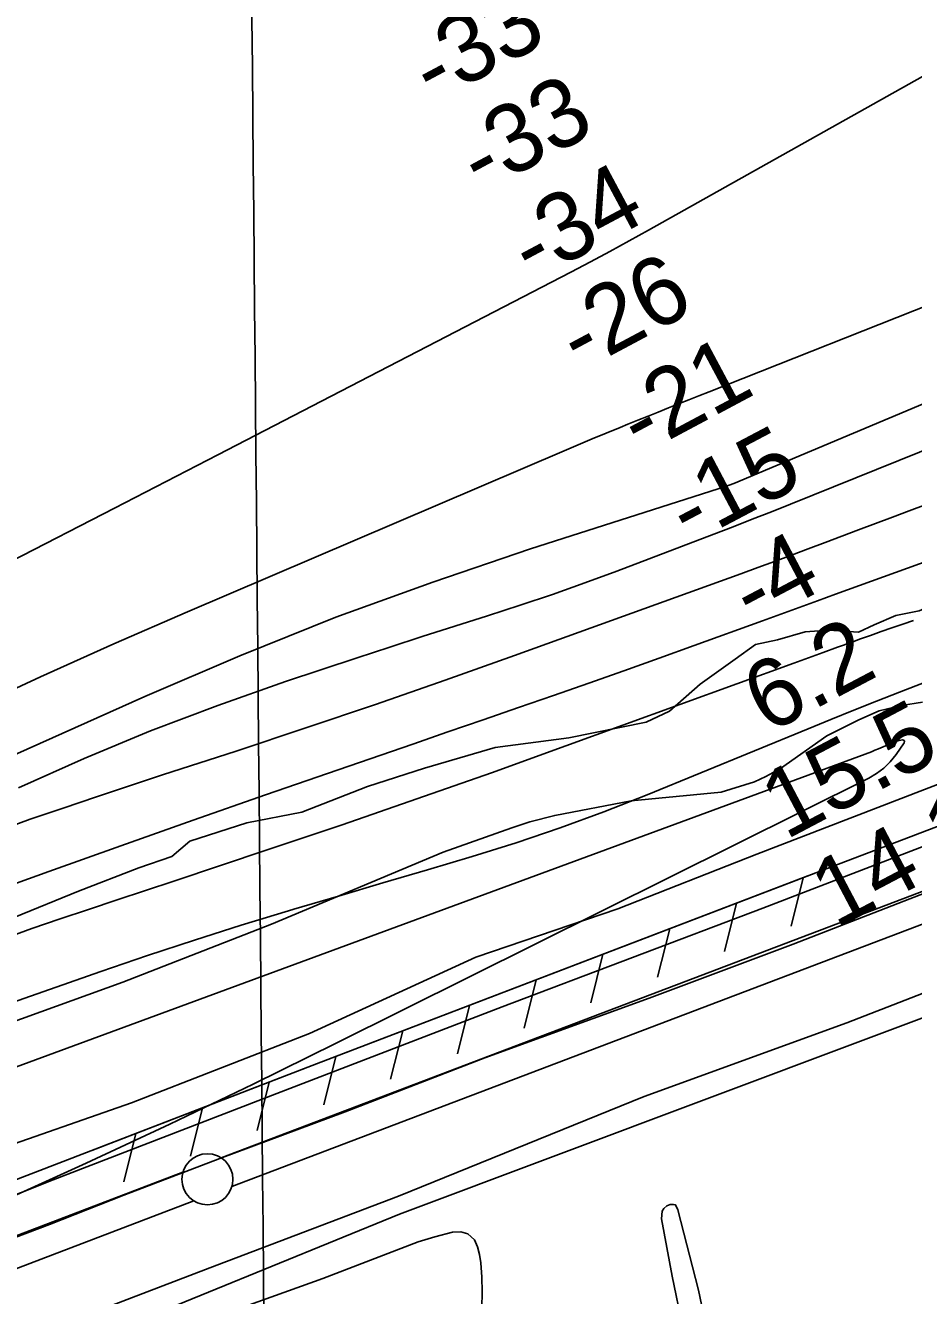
# Model space of a CAD drawing. Extents: x 3598634 to 3636690, y 517270 to 542944.
# Drawn here: x 3613087 to 3613957, y 532459 to 533703 of the extents above; entities that cross this region are included whole.
import ezdxf

# ---------------------------------------------------------------- set-up
doc = ezdxf.new("R2010")
doc.units = 0
for name, color, linetype in [('V-FLOD-BASE', 7, 'Continuous'), ('V-GRID-MAJR', 7, 'Continuous'), ('V-LEVE-TOET', 7, 'Continuous'), ('V-RIVR-EDGE', 7, 'Continuous'), ('V-RIVR-RANG', 7, 'Continuous'), ('V-ROAD-CNTR', 7, 'Continuous'), ('V-RRAP-FSHR', 7, 'Continuous'), ('V-SITE-VEGE', 7, 'Continuous'), ('V-SURV-LINE', 7, 'Continuous'), ('V-TOPO-DPTH', 7, 'Continuous'), ('V-TOPO-MINR', 7, 'Continuous'), ('V-TOPO-WATR', 7, 'Continuous')]:
    doc.layers.add(name, color=color, linetype=linetype)

msp = doc.modelspace()

# ---------------------------------------------------------------- linework, layer by layer
at = {"layer": 'V-FLOD-BASE'}
msp.add_lwpolyline([(3613000.302, 532486.936), (3613110.683, 532528.524), (3613183.67, 532557.436), (3613277.515, 532593.333), (3613400.362, 532638.807), (3613537.187, 532691.742), (3613698.191, 532750.407), (3613839.347, 532803.3640000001), (3613981.257, 532858.363), (3614114.5330000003, 532907.9670000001), (3614199.723, 532942.0380000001), (3614387.173, 533011.7930000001), (3614512.052, 533058.553)], dxfattribs=at)
at = {"layer": 'V-GRID-MAJR'}
msp.add_spline([(3613409.2970000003, 522775.228), (3613353.788, 528832.875), (3613298.25, 534893.607), (3613242.713, 540954.353), (3613242.685, 540957.422)], degree=3, dxfattribs=at)
at = {"layer": 'V-LEVE-TOET'}
for points in [[(3614422.54, 533072.111), (3614215.003, 532994.098), (3614015.61, 532917.911), (3613809.608, 532838.632), (3613554.259, 532741.774), (3613333.507, 532656.813), (3613114.281, 532572.372), (3612885.4050000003, 532481.254), (3612653.469, 532390.884), (3612445.931, 532312.8740000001), (3612222.6350000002, 532226.6240000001), (3612065.953, 532170.022), (3612060.235, 532167.986), (3612054.591, 532165.756), (3612049.024, 532163.331), (3612043.546, 532160.718), (3612038.16, 532157.916), (3612032.8740000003, 532154.932), (3612027.694, 532151.768), (3612022.626, 532148.43)], [(3614507.14, 532961.232), (3614278.741, 532870.968), (3614092.484, 532804.087), (3613891.77, 532726.185), (3613693.318, 532653.895), (3613452.736, 532556.443), (3613267.767, 532486.258), (3613039.861, 532398.8), (3612845.77, 532320.167), (3612548.486, 532209.698), (3612242.589, 532090.783), (3612175.54, 532059.893), (3612151.416, 532047.805), (3612126.054, 532029.349), (3612098.176, 532004.767), (3612075.654, 531978.178), (3612025.6380000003, 531901.806), (3611961.728, 531804.4890000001), (3611905.255, 531746.414), (3611847.997, 531692.41), (3611778.264, 531638.339)]]:
    msp.add_lwpolyline(points, dxfattribs=at)
at = {"layer": 'V-RIVR-EDGE'}
for points in [[(3613823.7760857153, 533101.4595198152), (3613850.80991655, 533109.1969191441), (3613874.226965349, 533110.9399954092), (3613903.038014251, 533109.0677740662), (3613918.6642243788, 533116.2330545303), (3613939.6977944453, 533125.1859440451), (3613962.5219424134, 533129.9321195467), (3613980.5509288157, 533137.6917852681), (3614035.8949421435, 533183.7800861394), (3614045.500109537, 533183.7563353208), (3614058.707214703, 533183.7236779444), (3614092.962734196, 533198.6471397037), (3614112.190882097, 533205.8035136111), (3614151.2282033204, 533212.3105784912), (3614202.276437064, 533220.5889237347), (3614225.717236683, 533231.9371673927), (3614250.9738494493, 533249.2841873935), (3614272.023748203, 533264.8406294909), (3614295.4600945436, 533274.3879042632), (3614341.111359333, 533285.0809011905), (3614383.749133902, 533290.9787365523), (3614401.7662448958, 533293.9358185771), (3614432.4064667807, 533303.465280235)], [(3613076.8977455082, 532829.5573908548), (3613139.395163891, 532855.216897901), (3613198.28322237, 532877.8836966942), (3613230.7288664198, 532889.2096739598), (3613248.1753429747, 532904.1746996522), (3613304.0499112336, 532922.0463368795), (3613358.1056974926, 532932.7185518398), (3613422.4026003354, 532957.7732826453), (3613478.277168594, 532975.6449198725), (3613547.364779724, 532995.8851915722), (3613619.427285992, 533005.3122278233), (3613695.106574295, 533020.7335871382), (3613717.9455665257, 533031.4829922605), (3613748.0270293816, 533057.8229812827), (3613782.3062996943, 533082.3516104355), (3613802.1525836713, 533096.7103754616), (3613823.7760857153, 533101.4595198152)]]:
    msp.add_lwpolyline(points, dxfattribs=at)
at = {"layer": 'V-ROAD-CNTR'}
msp.add_lwpolyline([(3612226.4165086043, 532062.082849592), (3612430.1341011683, 532146.2306812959), (3612651.0636593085, 532229.090515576), (3612941.725077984, 532339.909293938), (3613141.7286779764, 532411.4711508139), (3613453.6000542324, 532538.819896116), (3613757.318446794, 532652.6566684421), (3614058.088845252, 532765.6274424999), (3614367.371226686, 532889.3891949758), (3614416.655128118, 532906.56716062), (3614507.940945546, 532930.429112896), (3614637.907685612, 532981.4820107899), (3614761.996437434, 533030.3059131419), (3614915.0061314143, 533089.5087947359), (3615031.7688978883, 533135.0497036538)], dxfattribs=at)
at = {"layer": 'V-RRAP-FSHR'}
for p, q in [((3613849.05026333, 532868.3472370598), (3613837.1902870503, 532820.9783317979)), ((3613783.67539408, 532843.326287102), (3613771.814417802, 532795.9583818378)), ((3613718.299524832, 532818.306337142), (3613706.439548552, 532770.93743188)), ((3613652.9236555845, 532793.2853871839), (3613641.063679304, 532745.91748192)), ((3613587.548786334, 532768.265437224), (3613575.6888100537, 532720.896531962)), ((3613522.172917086, 532743.2444872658), (3613510.3129408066, 532695.8765820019)), ((3613456.7980478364, 532718.2245373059), (3613444.937071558, 532670.8556320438)), ((3613391.422178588, 532693.203587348), (3613379.5622023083, 532645.8356820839)), ((3613326.08130927, 532668.0926375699), (3613314.3143328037, 532620.700732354)), ((3613260.755439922, 532642.944687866), (3613248.987463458, 532595.55278265)), ((3613195.4285705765, 532617.795738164), (3613183.6605941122, 532570.4048329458))]:
    msp.add_line(p, q, dxfattribs=at)
for points in [[(3610481.36199872, 531014.916943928), (3610518.104925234, 531016.4149409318), (3610542.9578755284, 531035.0839035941), (3610817.540326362, 531253.668466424), (3610959.6230421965, 531343.0142877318), (3611372.879215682, 531575.953821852), (3611600.4127606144, 531710.30955314), (3611708.441544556, 531774.8914239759), (3611794.450372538, 531830.618312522), (3611891.671178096, 531952.950067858), (3611922.576116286, 532018.367937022), (3611961.0420393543, 532105.7287623), (3611976.132009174, 532125.9887217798), (3611993.926973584, 532140.8886919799), (3612020.040921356, 532159.111655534), (3612058.2698448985, 532179.071615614), (3612392.982175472, 532307.350359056), (3612844.3952726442, 532482.6610084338), (3613372.504216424, 532685.9636018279), (3613879.357202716, 532879.9462138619), (3614277.50940641, 533031.947909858), (3614728.456504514, 533206.493560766)], [(3613152.215657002, 532601.1607714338), (3613372.504216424, 532685.9636018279), (3613853.466254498, 532870.03723368)]]:
    msp.add_lwpolyline(points, dxfattribs=at)
at = {"layer": 'V-SITE-VEGE'}
for points in [[(3614426.144, 533134.792), (3614332.272, 533096.9180000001), (3614226.044, 533062.452), (3614112.9390000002, 533015.6140000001), (3613990.61, 532963.718), (3613803.6180000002, 532891.446), (3613667.415, 532837.936), (3613528.485, 532790.582), (3613365.407, 532715.732), (3613191.112, 532647.765), (3613048.727, 532598.078)], [(3613068.128, 532724.628), (3613182.801, 532766.076), (3613328.24, 532822.7170000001), (3613496.35, 532893.351), (3613563.694, 532917.21), (3613581.397, 532923.084), (3613605.654, 532929.375), (3613680.3710000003, 532943.633), (3613768.611, 532952.18), (3613801.328, 532962.368), (3613812.481, 532967.437), (3613826.707, 532975.22), (3613872.0330000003, 533007.449), (3613903.566, 533023.03), (3613923.569, 533031.998), (3613945.13, 533037.12), (3613965.932, 533040.309)], [(3613268.565, 532436.008), (3613378.443, 532475.68), (3613472.0300000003, 532511.575), (3613488.3140000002, 532516.371), (3613505.615, 532521.174), (3613513.6410000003, 532521.471), (3613520.531, 532519.339), (3613527.058, 532513.639), (3613529.896, 532506.772), (3613531.846, 532499.267), (3613533.29, 532490.866), (3613534.252, 532476.855), (3613534.705, 532462.589), (3613534.279, 532446.916)]]:
    msp.add_lwpolyline(points, dxfattribs=at)
msp.add_lwpolyline([(3613726.326, 532543.09), (3613746.431, 532464.1190000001), (3613757.972, 532409.667), (3613761.4250000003, 532384.863), (3613760.96, 532375.649), (3613758.687, 532369.751), (3613754.865, 532366.151), (3613751.2830000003, 532366.132), (3613746.9250000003, 532367.6460000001), (3613740.977, 532379.899), (3613720.52, 532477.806), (3613710.251, 532534.052), (3613710.98, 532541.478), (3613712.502, 532544.3), (3613715.304, 532546.8740000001), (3613718.88, 532548.171), (3613721.952, 532548.183), (3613724, 532547.685)], close=True, dxfattribs=at)
at = {"layer": 'V-SURV-LINE'}
for points in [[(3613278.8365126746, 532593.9802002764), (3614936.6002117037, 533223.8538016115)], [(3614947.264207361, 533195.8131297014), (3613289.5005082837, 532565.9395283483)], [(3612136.4876135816, 532157.6203128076), (3613241.4773970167, 532579.7468970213)], [(3613252.193056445, 532551.7259271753), (3612147.2032729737, 532129.599342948)]]:
    msp.add_lwpolyline(points, dxfattribs=at)
msp.add_circle((3613265.49586, 532572.8651199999), 25, dxfattribs=at)
at = {"layer": 'V-TOPO-DPTH'}
for points in [[(3611819.3313301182, 532526.5151463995), (3612734.6481101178, 533003.965567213), (3612751.4151440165, 533012.6914705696), (3612768.193138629, 533021.3961986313), (3612784.987574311, 533030.0691637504), (3612801.7929707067, 533038.7209535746), (3612971.332383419, 533125.8007775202), (3613072.8863420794, 533178.0335070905), (3613174.401147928, 533230.3421156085), (3613275.8572245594, 533282.7645425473), (3613377.274148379, 533335.2628484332), (3613621.4071012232, 533461.8115098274), (3613640.541545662, 533471.8522166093), (3613659.6072954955, 533482.020188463), (3613678.57000342, 533492.3790579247), (3613697.4640167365, 533502.8651924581), (3614185.949509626, 533777.1900551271)], [(3614185.949509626, 533777.1900551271), (3613697.4640167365, 533502.8651924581), (3613678.57000342, 533492.3790579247), (3613659.6072954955, 533482.020188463), (3613640.541545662, 533471.8522166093), (3613621.4071012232, 533461.8115098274), (3613377.274148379, 533335.2628484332), (3613275.8572245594, 533282.7645425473), (3613174.401147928, 533230.3421156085), (3613072.8863420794, 533178.0335070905), (3612971.332383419, 533125.8007775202), (3612801.7929707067, 533038.7209535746), (3612784.987574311, 533030.0691637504), (3612768.193138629, 533021.3961986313), (3612751.4151440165, 533012.6914705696), (3612734.6481101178, 533003.965567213), (3611819.3313301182, 532526.5151463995)], [(3613030.700296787, 533032.0868591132), (3613102.0422444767, 533065.2400696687), (3613173.847296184, 533097.3779510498), (3613245.9610839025, 533128.8389463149), (3613614.998203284, 533286.7319593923), (3613628.624368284, 533292.5170105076), (3613642.2717219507, 533298.2512363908), (3613655.950858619, 533303.9092244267), (3613669.651183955, 533309.5163872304), (3613677.225328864, 533312.5916317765), (3613687.1571598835, 533316.6163938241), (3613697.092571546, 533320.6322801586), (3613707.0333541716, 533324.6348529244), (3613716.977717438, 533328.6285499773), (3613726.927610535, 533332.6084445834), (3613736.8812960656, 533336.5788117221), (3613746.840670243, 533340.5348876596), (3613756.8038368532, 533344.4814361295), (3613990.93811325, 533437.0309263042), (3614114.926412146, 533485.7275249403), (3614239.055173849, 533534.0610391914), (3614363.394629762, 533581.8499268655), (3614487.874548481, 533629.2757301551)], [(3614487.874548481, 533629.2757301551), (3614363.394629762, 533581.8499268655), (3614239.055173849, 533534.0610391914), (3614114.926412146, 533485.7275249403), (3613990.93811325, 533437.0309263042), (3613756.8038368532, 533344.4814361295), (3613746.840670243, 533340.5348876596), (3613736.8812960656, 533336.5788117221), (3613726.927610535, 533332.6084445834), (3613716.977717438, 533328.6285499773), (3613707.0333541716, 533324.6348529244), (3613697.092571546, 533320.6322801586), (3613687.1571598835, 533316.6163938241), (3613677.225328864, 533312.5916317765), (3613669.651183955, 533309.5163872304), (3613655.950858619, 533303.9092244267), (3613642.2717219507, 533298.2512363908), (3613628.624368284, 533292.5170105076), (3613614.998203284, 533286.7319593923), (3613245.9610839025, 533128.8389463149), (3613173.847296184, 533097.3779510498), (3613102.0422444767, 533065.2400696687), (3613030.700296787, 533032.0868591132)], [(3613984.7652584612, 533293.9619254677), (3613836.60483101, 533234.3696623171), (3613817.872861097, 533226.8967684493), (3613799.1132249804, 533219.4945739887), (3613780.3120895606, 533212.1984286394), (3613761.4832879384, 533204.9729826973), (3613666.5459908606, 533168.8485220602), (3613635.1119050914, 533157.2163891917), (3613603.543909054, 533145.9713719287), (3613571.7750476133, 533135.3070280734), (3613539.8722759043, 533125.0297998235), (3613507.897887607, 533114.9534997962), (3613475.9620222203, 533104.7576958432), (3613444.0839412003, 533094.382636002), (3613412.244383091, 533083.8880722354), (3613342.0719522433, 533060.5399608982), (3613275.6294228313, 533037.1413757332), (3613209.790999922, 533012.2265986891), (3613144.858736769, 532985.0375338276), (3613080.5305801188, 532956.332277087)], [(3613080.5305801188, 532956.332277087), (3613144.858736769, 532985.0375338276), (3613209.790999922, 533012.2265986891), (3613275.6294228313, 533037.1413757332), (3613342.0719522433, 533060.5399608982), (3613412.244383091, 533083.8880722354), (3613444.0839412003, 533094.382636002), (3613475.9620222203, 533104.7576958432), (3613507.897887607, 533114.9534997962), (3613539.8722759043, 533125.0297998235), (3613571.7750476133, 533135.3070280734), (3613603.543909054, 533145.9713719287), (3613635.1119050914, 533157.2163891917), (3613666.5459908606, 533168.8485220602), (3613761.4832879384, 533204.9729826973), (3613780.3120895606, 533212.1984286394), (3613799.1132249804, 533219.4945739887), (3613817.872861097, 533226.8967684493), (3613836.60483101, 533234.3696623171), (3613984.7652584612, 533293.9619254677)], [(3614033.562915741, 533201.4897716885), (3613880.7332195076, 533146.03000332), (3613862.868403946, 533139.5474408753), (3613845.003447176, 533133.0652676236), (3613827.138278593, 533126.5836781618), (3613809.2729688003, 533120.1024778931), (3613742.160555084, 533095.7565902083), (3613707.8302627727, 533083.3873170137), (3613673.464584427, 533071.1178422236), (3613639.0458270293, 533058.9980650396), (3613604.591683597, 533046.9780862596), (3613570.10711707, 533035.0442059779), (3613535.617374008, 533023.1253208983), (3613501.119866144, 533011.2289286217), (3613466.6171817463, 532999.3475315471), (3613393.5284327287, 532974.2052313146), (3613322.5322908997, 532949.6083392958), (3613251.6092117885, 532924.8040015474), (3613180.795726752, 532899.6884952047), (3613110.055304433, 532874.3655431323), (3612966.721819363, 532822.7011697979)], [(3612966.721819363, 532822.7011697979), (3613110.055304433, 532874.3655431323), (3613180.795726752, 532899.6884952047), (3613251.6092117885, 532924.8040015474), (3613322.5322908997, 532949.6083392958), (3613393.5284327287, 532974.2052313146), (3613466.6171817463, 532999.3475315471), (3613501.119866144, 533011.2289286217), (3613535.617374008, 533023.1253208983), (3613570.10711707, 533035.0442059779), (3613604.591683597, 533046.9780862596), (3613639.0458270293, 533058.9980650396), (3613673.464584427, 533071.1178422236), (3613707.8302627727, 533083.3873170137), (3613742.160555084, 533095.7565902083), (3613809.2729688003, 533120.1024778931), (3613827.138278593, 533126.5836781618), (3613845.003447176, 533133.0652676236), (3613862.868403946, 533139.5474408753), (3613880.7332195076, 533146.03000332), (3614033.562915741, 533201.4897716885)], [(3614088.3550961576, 533106.3703455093), (3613943.338112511, 533050.0561320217), (3613920.8864252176, 533041.2617001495), (3613898.469699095, 533032.3797806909), (3613876.105414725, 533023.3666298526), (3613853.7760915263, 533014.2659914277), (3613696.0703917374, 532949.4511752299), (3613653.757304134, 532932.8192572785), (3613611.1339574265, 532917.0684898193), (3613568.0452220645, 532902.6394480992), (3613524.6462275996, 532889.0915568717), (3613481.017668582, 532876.1936932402), (3613437.3939661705, 532863.2794412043), (3613393.777548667, 532850.3406065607), (3613350.165987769, 532837.3853835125), (3613344.864760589, 532835.8089785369), (3613298.7104037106, 532821.730759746), (3613252.6948836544, 532807.222734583), (3613206.88761883, 532792.0699998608), (3613161.2191908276, 532776.487458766), (3613010.833832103, 532723.9926749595)]]:
    msp.add_lwpolyline(points, dxfattribs=at)
at = {"layer": 'V-TOPO-MINR'}
for points in [[(3611819.3313301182, 532526.5151463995), (3612734.6481101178, 533003.965567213), (3612751.4151440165, 533012.6914705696), (3612768.193138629, 533021.3961986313), (3612784.987574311, 533030.0691637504), (3612801.7929707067, 533038.7209535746), (3612971.332383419, 533125.8007775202), (3613072.8863420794, 533178.0335070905), (3613174.401147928, 533230.3421156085), (3613275.8572245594, 533282.7645425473), (3613377.274148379, 533335.2628484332), (3613621.4071012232, 533461.8115098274), (3613640.541545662, 533471.8522166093), (3613659.6072954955, 533482.020188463), (3613678.57000342, 533492.3790579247), (3613697.4640167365, 533502.8651924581), (3614185.949509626, 533777.1900551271)], [(3613030.700296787, 533032.0868591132), (3613102.0422444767, 533065.2400696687), (3613173.847296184, 533097.3779510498), (3613245.9610839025, 533128.8389463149), (3613614.998203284, 533286.7319593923), (3613628.624368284, 533292.5170105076), (3613642.2717219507, 533298.2512363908), (3613655.950858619, 533303.9092244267), (3613669.651183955, 533309.5163872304), (3613677.225328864, 533312.5916317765), (3613687.1571598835, 533316.6163938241), (3613697.092571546, 533320.6322801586), (3613707.0333541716, 533324.6348529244), (3613716.977717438, 533328.6285499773), (3613726.927610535, 533332.6084445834), (3613736.8812960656, 533336.5788117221), (3613746.840670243, 533340.5348876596), (3613756.8038368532, 533344.4814361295), (3613990.93811325, 533437.0309263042), (3614114.926412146, 533485.7275249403), (3614239.055173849, 533534.0610391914), (3614363.394629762, 533581.8499268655), (3614487.874548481, 533629.2757301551)], [(3612917.205176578, 532917.5238498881), (3613204.1887317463, 533045.9624583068), (3613297.2596155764, 533085.7724069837), (3613391.1314751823, 533123.4889194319), (3613486.20479845, 533158.0652775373), (3613582.0790974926, 533190.5481994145), (3613773.981510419, 533252.0292246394), (3613774.507337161, 533252.1960386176), (3613776.6153571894, 533252.8473354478), (3613781.193859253, 533254.6073462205), (3614202.48517906, 533431.7855952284), (3614296.768311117, 533470.5611714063), (3614391.4424538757, 533508.3336941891), (3614486.7031126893, 533544.60163688)], [(3613080.5305801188, 532956.332277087), (3613144.858736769, 532985.0375338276), (3613209.790999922, 533012.2265986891), (3613275.6294228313, 533037.1413757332), (3613342.0719522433, 533060.5399608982), (3613412.244383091, 533083.8880722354), (3613444.0839412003, 533094.382636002), (3613475.9620222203, 533104.7576958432), (3613507.897887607, 533114.9534997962), (3613539.8722759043, 533125.0297998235), (3613571.7750476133, 533135.3070280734), (3613603.543909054, 533145.9713719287), (3613635.1119050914, 533157.2163891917), (3613666.5459908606, 533168.8485220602), (3613761.4832879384, 533204.9729826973), (3613780.3120895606, 533212.1984286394), (3613799.1132249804, 533219.4945739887), (3613817.872861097, 533226.8967684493), (3613836.60483101, 533234.3696623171), (3613984.7652584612, 533293.9619254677)], [(3613059.936215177, 532913.9556384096), (3613092.037522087, 532925.5942944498), (3613124.3695652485, 532936.6482159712), (3613156.7396001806, 532947.5887499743), (3613189.166622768, 532958.3592026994), (3613221.6316371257, 532969.0162679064), (3613293.632141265, 532992.4421984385), (3613362.0133056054, 533015.0552626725), (3613430.2443718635, 533038.1056727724), (3613498.2502909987, 533061.8121016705), (3613566.1061120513, 533085.9558764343), (3613788.019774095, 533166.1209262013), (3613804.5412030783, 533172.1368243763), (3613821.041864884, 533178.2087177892), (3613837.511375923, 533184.36460406), (3613853.9601197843, 533190.576485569), (3613870.395213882, 533196.8252879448), (3613886.8328767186, 533203.0673195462), (3613903.274392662, 533209.2991949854), (3613919.718477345, 533215.5242996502), (3613919.80812276, 533215.5582043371), (3613936.3162854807, 533221.7480158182), (3613952.847551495, 533227.874942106), (3613969.4134724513, 533233.9075406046)], [(3613066.0615106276, 532808.6126252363), (3613093.641552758, 532818.5187413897), (3613121.362946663, 532828.0438192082), (3613149.188576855, 532837.2884929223), (3613177.0116953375, 532846.5407146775), (3613204.8310462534, 532855.8042584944), (3613232.64788546, 532865.0753503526), (3613323.955260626, 532895.5278872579), (3613397.3224101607, 532920.3222729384), (3613470.554254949, 532945.505087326), (3613543.5831426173, 532971.2705447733), (3613616.476725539, 532997.4244309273), (3613840.0026992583, 533078.6310621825), (3613854.2194425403, 533083.7962363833), (3613868.436077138, 533088.9617096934), (3613882.652548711, 533094.1276316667), (3613896.8689115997, 533099.2938527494), (3613904.2336518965, 533101.9703282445), (3613914.778840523, 533105.7665000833), (3613925.339064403, 533109.5199611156), (3613935.9218411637, 533113.2093559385), (3613946.519653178, 533116.8560399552), (3613957.1279446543, 533120.473024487)], [(3613010.833832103, 532723.9926749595), (3613161.2191908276, 532776.487458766), (3613206.88761883, 532792.0699998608), (3613252.6948836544, 532807.222734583), (3613298.7104037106, 532821.730759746), (3613344.864760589, 532835.8089785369), (3613350.165987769, 532837.3853835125), (3613393.777548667, 532850.3406065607), (3613437.3939661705, 532863.2794412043), (3613481.017668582, 532876.1936932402), (3613524.6462275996, 532889.0915568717), (3613568.0452220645, 532902.6394480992), (3613611.1339574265, 532917.0684898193), (3613653.757304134, 532932.8192572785), (3613696.0703917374, 532949.4511752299), (3613853.7760915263, 533014.2659914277), (3613876.105414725, 533023.3666298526), (3613898.469699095, 533032.3797806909), (3613920.8864252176, 533041.2617001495), (3613943.338112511, 533050.0561320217), (3614088.3550961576, 533106.3703455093)], [(3611945.2200455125, 532128.3498760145), (3611957.7075775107, 532138.7491644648), (3611973.086673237, 532150.7450536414), (3612016.8369514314, 532183.2102091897), (3612020.4055441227, 532185.6732079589), (3612024.134516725, 532187.885894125), (3612070.5974927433, 532213.3440727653), (3612095.848614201, 532226.891500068), (3612121.2529022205, 532240.1387709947), (3612146.8869400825, 532252.9358073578), (3612172.674144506, 532265.4326873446), (3612964.826452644, 532640.7286406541), (3612968.863405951, 532642.5923598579), (3612972.9237819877, 532644.402091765), (3612977.019292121, 532646.1308427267), (3612981.138224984, 532647.8056063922), (3613023.652073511, 532663.5845761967), (3613028.536517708, 532664.7633553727), (3613915.865461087, 532991.7704232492), (3613919.2728372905, 532993.2750403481), (3613922.7014775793, 532994.7305508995), (3613937.2137532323, 533000.7685732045), (3613941.5896265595, 533002.3557101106)], [(3613941.5896265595, 533002.3557101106), (3613946.0935850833, 533003.5311370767), (3613947.2549685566, 533003.2672175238), (3613948.0264089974, 533002.7434197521), (3613948.212934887, 533001.8298046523), (3613948.009517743, 533000.6563113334), (3613939.9071213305, 532988.9151332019), (3613934.268518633, 532981.9517942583), (3613928.043235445, 532975.6650837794), (3613920.9379315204, 532970.3933159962), (3613913.2459471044, 532965.7981766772), (3613391.5093873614, 532706.0822927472), (3613310.2261730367, 532666.2136160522), (3613228.6398221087, 532626.9849812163), (3613146.598766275, 532588.7164091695), (3613064.254573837, 532551.0878789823), (3613031.267169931, 532536.2470956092), (3612965.011500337, 532506.937397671), (3612898.5189114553, 532478.1851715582), (3612831.670943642, 532450.2691531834), (3612764.5860565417, 532422.9106066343), (3612330.695626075, 532249.1271514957)]]:
    msp.add_lwpolyline(points, dxfattribs=at)
at = {"layer": 'V-TOPO-WATR'}
msp.add_lwpolyline([(3612966.721819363, 532822.7011697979), (3613110.055304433, 532874.3655431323), (3613180.795726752, 532899.6884952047), (3613251.6092117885, 532924.8040015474), (3613322.5322908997, 532949.6083392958), (3613393.5284327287, 532974.2052313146), (3613466.6171817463, 532999.3475315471), (3613501.119866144, 533011.2289286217), (3613535.617374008, 533023.1253208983), (3613570.10711707, 533035.0442059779), (3613604.591683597, 533046.9780862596), (3613639.0458270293, 533058.9980650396), (3613673.464584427, 533071.1178422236), (3613707.8302627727, 533083.3873170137), (3613742.160555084, 533095.7565902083), (3613809.2729688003, 533120.1024778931), (3613827.138278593, 533126.5836781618), (3613845.003447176, 533133.0652676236), (3613862.868403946, 533139.5474408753), (3613880.7332195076, 533146.03000332), (3614033.562915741, 533201.4897716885)], dxfattribs=at)

# ---------------------------------------------------------------- texts
at = {"layer": 'V-RIVR-RANG'}
for s, height, rotation, p in [('-33', 67.00000000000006, 28.122361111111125, (3613486.316194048, 533626.7859979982)), ('-33', 67.00000000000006, 28.122361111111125, (3613533.233194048, 533538.4759979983)), ('-34', 67.00000000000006, 28.122361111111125, (3613583.1754945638, 533451.7813412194)), ('-26', 67.00000000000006, 28.122361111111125, (3613630.3251330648, 533363.5956753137)), ('-21', 67.00000000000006, 28.122361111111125, (3613689.5719736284, 533281.8743822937)), ('-15', 67, 27.838325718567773, (3613737.352517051, 533194.3969907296)), ('-4', 67, 27.838325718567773, (3613799.430897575, 533114.0936452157)), ('6.2', 67, 27.838325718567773, (3613814.159120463, 533008.7839018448)), ('15.5', 67, 27.838325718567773, (3613831.687367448, 532904.9533100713)), ('14.1', 67, 27.838325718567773, (3613880.7036355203, 532817.7509237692))]:
    msp.add_text(s, height=height, rotation=rotation, dxfattribs=at).set_placement(p)

doc.saveas('drawing.dxf')
